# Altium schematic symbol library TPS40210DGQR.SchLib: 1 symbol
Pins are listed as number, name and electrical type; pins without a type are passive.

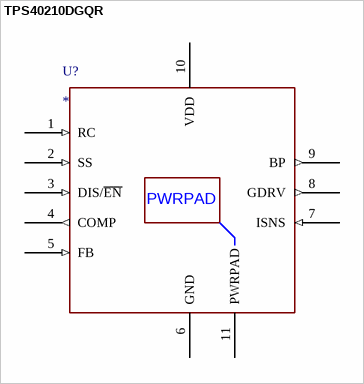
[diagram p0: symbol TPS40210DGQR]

## TPS40210DGQR
designator U?
GENERIC PART DESCRIPTION: 4.5-V TO 52-V INPUT CURRENT MODE BOOST CONTROLLER; ORDERABLE DEVICE NUMBER: TPS40210DGQR
footprint MSOP_DGQ10_EP1P88X1P57
pins: 1 RC (in), 2 SS (in), 3 DIS/~{EN} (in), 4 COMP (out), 5 FB (in), 6 GND (power), 7 ISNS (in), 8 GDRV (out), 9 BP (out), 10 VDD (power), 11 PWRPAD (power)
